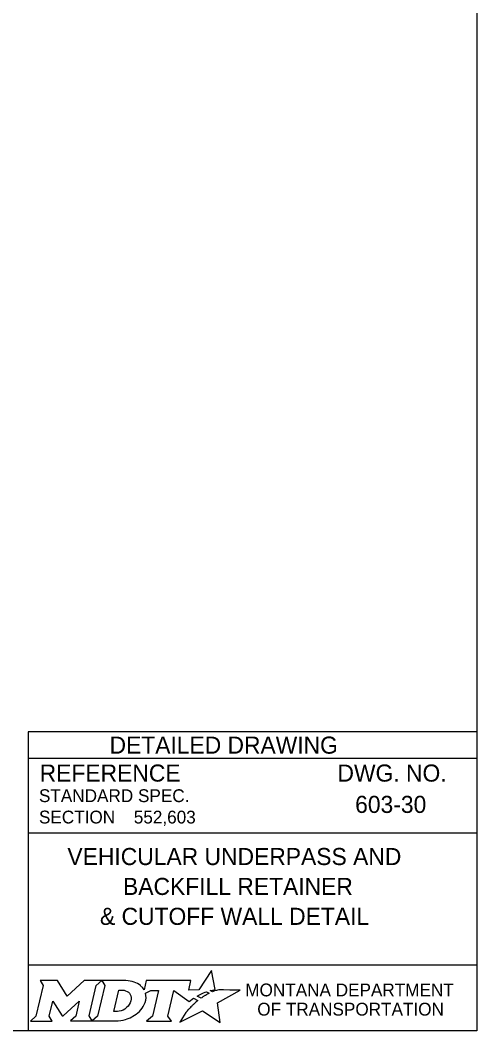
# Model space of a CAD drawing. Extents: x 49991.4 to 50021, y 49987.6 to 50011.4.
# Drawn here: x 50014.613 to 50016.75, y 49987.799 to 49992.53 of the extents above; entities that cross this region are included whole.
import ezdxf

# ---------------------------------------------------------------- set-up
doc = ezdxf.new("R2010")
doc.units = 0
for name, color, linetype in [('Default', 7, 'Continuous'), ('Level 1', 7, 'Continuous'), ('Level 2', 7, 'Continuous'), ('Level 5', 7, 'Continuous')]:
    doc.layers.add(name, color=color, linetype=linetype)

msp = doc.modelspace()

# ---------------------------------------------------------------- linework, layer by layer
at = {"layer": 'Default'}
for points in [[(50015.5126, 49987.9811), (50015.5023, 49987.9867), (50015.5139, 49987.9895), (50015.5255, 49987.9915), (50015.5081, 49988.0816), (50015.4486, 49987.9903), (50015.4013, 49987.9896), (50015.4116, 49988.0337), (50015.2024, 49988.0338), (50015.1923, 49987.9913), (50015.1865, 49987.9996)], [(50014.7056, 49988.0338), (50014.7197, 49988.0104), (50014.6862, 49987.8671), (50014.6605, 49987.8446), (50014.7621, 49987.8446), (50014.7486, 49987.8674), (50014.7648, 49987.9375), (50014.8085, 49987.8685), (50014.8138, 49987.8685), (50014.8889, 49987.938), (50014.8725, 49987.8669), (50014.8478, 49987.8449), (50014.9494, 49987.8449), (50014.9356, 49987.8682), (50014.9688, 49988.0106)], [(50014.9688, 49988.0106), (50014.9941, 49988.0338), (50014.9117, 49988.0338), (50014.8321, 49987.9608), (50014.7876, 49988.0335), (50014.7056, 49988.0338)], [(50015.1077, 49988.0338), (50014.9941, 49988.0338), (50015.0088, 49988.0109), (50014.9749, 49987.8671), (50014.9494, 49987.8449), (50015.06, 49987.8449)], [(50015.1317, 49987.9471), (50015.1305, 49987.939), (50015.1273, 49987.9297), (50015.1231, 49987.9215), (50015.1175, 49987.914), (50015.111, 49987.9071), (50015.1031, 49987.9008), (50015.0948, 49987.8961), (50015.0857, 49987.8922), (50015.0766, 49987.8899), (50015.0674, 49987.889), (50015.0515, 49987.889), (50015.0751, 49987.989), (50015.0911, 49987.989), (50015.0987, 49987.9884), (50015.1063, 49987.9865), (50015.1129, 49987.9835), (50015.119, 49987.9793), (50015.1238, 49987.9743), (50015.1275, 49987.9683), (50015.1302, 49987.9621), (50015.1318, 49987.9547), (50015.1318, 49987.9517), (50015.1317, 49987.9471)], [(50015.1991, 49987.9747), (50015.2237, 49987.9878), (50015.2606, 49987.9878), (50015.232, 49987.8673), (50015.2045, 49987.8446), (50015.3207, 49987.8446), (50015.3037, 49987.8675), (50015.3319, 49987.9877), (50015.4032, 49987.936), (50015.4243, 49987.9511), (50015.444, 49987.9402)], [(50015.3882, 49987.8843), (50015.3729, 49987.8599), (50015.3682, 49987.8524), (50015.3624, 49987.8438), (50015.3601, 49987.8395), (50015.4654, 49987.8926), (50015.5493, 49987.8375), (50015.5362, 49987.9302), (50015.6431, 49987.9886), (50015.5938, 49987.9894), (50015.5637, 49987.9898), (50015.5429, 49987.9901), (50015.5361, 49987.9886), (50015.5312, 49987.9874), (50015.5228, 49987.9851), (50015.5126, 49987.9811)], [(50015.4622, 49987.9535), (50015.4598, 49987.9518), (50015.4415, 49987.9614), (50015.4518, 49987.9671), (50015.4559, 49987.9693), (50015.4645, 49987.9733), (50015.4702, 49987.9759), (50015.4781, 49987.9789), (50015.4854, 49987.9816), (50015.4972, 49987.9742), (50015.4932, 49987.9721), (50015.4886, 49987.9696), (50015.4844, 49987.9674), (50015.4794, 49987.9645), (50015.4775, 49987.9634), (50015.4748, 49987.9618), (50015.4723, 49987.9604), (50015.47, 49987.9588), (50015.4674, 49987.957), (50015.4647, 49987.9552), (50015.4622, 49987.9535)], [(50015.4021, 49987.9004), (50015.4021, 49987.9004)], [(50015.1057, 49987.8522), (50015.1141, 49987.8548), (50015.1271, 49987.8602), (50015.1475, 49987.8712)]]:
    msp.add_lwpolyline(points, dxfattribs=at)
for centre, radius, start, end in [((50015.0868, 49987.9727), 0.1183, 300.9103, 339.1383), ((50015.1308, 49987.9554), 0.0709, 339.5329, 15.8582)]:
    msp.add_arc(centre, radius, start, end, dxfattribs=at)
for centre, major_axis, ratio, start_param, end_param in [((50015.1056, 49987.9864), (0.0834, -0.0037), 0.568097, 0.61298, 1.570796), ((50015.1612, 49987.9937), (0.0361, -0.0295), 0.469099, 1.225588, 1.570796), ((50015.4329, 49987.9305), (-0.0112, -0.0097), 0.021651, 3.157348, 6.283185), ((50015.3952, 49987.8923), (-0.00694, -0.00806), 0.008222, 0, 3.137361), ((50015.4119, 49987.9106), (-0.0098, -0.0102), 0.016458, 3.141593, 6.279097), ((50015.0603, 49987.9932), (0, 0.1484), 0.987302, 3.139398, 3.456847)]:
    msp.add_ellipse(centre, major_axis=major_axis, ratio=ratio, start_param=start_param, end_param=end_param, dxfattribs=at)
at = {"layer": 'Level 1'}
msp.add_lwpolyline([(49999.3835, 49998.9992), (50016.7501, 49998.9992), (50016.7501, 49987.7988), (49999.3835, 49987.7988)], close=True, dxfattribs=at)
at = {"layer": 'Level 5'}
for p, q in [((50016.7501, 49989.1988), (50014.6501, 49989.1988)), ((50014.6501, 49989.1988), (50014.6501, 49987.7988)), ((50016.7501, 49989.0738), (50014.6501, 49989.0738)), ((50016.7501, 49988.7238), (50014.6501, 49988.7238)), ((50016.7501, 49988.1057), (50014.6501, 49988.1057))]:
    msp.add_line(p, q, dxfattribs=at)

# ---------------------------------------------------------------- texts
at = {"layer": 'Default'}
for s, p in [('MONTANA DEPARTMENT', (50015.6663, 49987.96)), ('OF TRANSPORTATION', (50015.7225, 49987.87))]:
    msp.add_text(s, height=0.06, dxfattribs=at).set_placement(p)
at = {"layer": 'Level 2'}
for s, height, p in [('603-30', 0.08, (50016.1806, 49988.8187)), ('552,603', 0.06, (50015.1444, 49988.7693)), ('VEHICULAR UNDERPASS AND', 0.08, (50014.8336, 49988.5747)), ('BACKFILL RETAINER', 0.08, (50015.094, 49988.4347)), ('& CUTOFF WALL DETAIL', 0.08, (50014.986, 49988.2947))]:
    msp.add_text(s, height=height, dxfattribs=at).set_placement(p)
at = {"layer": 'Level 5'}
for s, height, p in [('DETAILED DRAWING', 0.0799, (50015.0311, 49989.0963)), ('REFERENCE', 0.08, (50014.7037, 49988.9654)), ('DWG. NO.', 0.08, (50016.0979, 49988.9654)), ('STANDARD SPEC.', 0.06, (50014.7004, 49988.8694)), ('SECTION', 0.06, (50014.7004, 49988.7694))]:
    msp.add_text(s, height=height, dxfattribs=at).set_placement(p)

doc.saveas('drawing.dxf')
